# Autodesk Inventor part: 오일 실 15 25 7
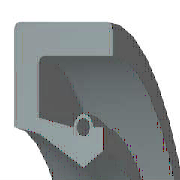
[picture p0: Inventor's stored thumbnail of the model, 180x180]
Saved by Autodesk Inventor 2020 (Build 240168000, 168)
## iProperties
Created: 2012-02
Part Number: 오일 실 15 25 7
Material: 고무
Description: 오일-실
Document SubType Name: Modeling
Standard: KS B 2804
Designer: mduedu
Standards Organization: KS
Language: ko-KR
Size Designation: S - 15 25 7
Categories: <MemberInstance><Categories><Category DisplayName="샤프트 부품" InternalName="7f7aeb1f-a693-4053-b835-cee3144e0d98" Mnemonic="SHFT"><Category DisplayName="실링" Intern
Density: 0.93 g/cm^3
Appearance: 고무 - 검은색 - 버전 1.1
IsCustomPart: 1
Author: mduedu
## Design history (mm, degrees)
revolve "본체" stored, may be unused: angle "d17" = 90 deg
revolve "스프링1" stored, may be unused: angle "d18" = 90 deg
body "Solid1"
sketch "스케치1"
  geometry: L1 (0, 12.5)-(7, 12.5); L2 (7, 12.5)-(7, 11.25); L3 (7, 11.25)-(1.75, 11.25); L4 (0, 12.5)-(0, 9.6); L5 (0, 9.6)-(1.75, 9.25); L6 (1.75, 9.25)-(4.9, 7.5); L7 (4.9, 7.5)-(0, 7.5); L8 (6.3, 8.375)-(6.3, 9.6); L9 (0, 0)-(9.586, 0) reference; L10 (4.9, 7.5)-(6.3, 8.375); L11 (0, 18)-(0, -3) reference; L12 (-1.917, 0)-(11.503, 0) reference; L13 (4.2, 9.6)-(1.75, 10.09); L14 (1.75, 10.09)-(1.75, 11.25); L15 (6.3, 9.6)-(5.6, 9.6); C1 r 0.455 at (4.9, 9.6); A1 r 0.7 centre (4.9, 9.6) between (5.6, 9.6) and (4.2, 9.6)
  constraints: 26 end point, 5 horizontal alignment, 4 perpendicular, 2 centre point, 2 collinear, 2 horizontal, 2 parallel, 2 point on circle, 2 point on line, 2 vertical alignment, 1 coincident
  dimensions: "d0" = 25 diameter of L1 L9 (= SD2); "d1" = 16.75 diameter of L8.start L9 (= ABDM); "d2" = 1.25 distance of L1.end L2.end (computed from SD); "d3" = 0.91 diameter of C1 (= SPDI); "d4" = 1.4 diameter of A1 (= SPDA); "d5" = 15 diameter of L6.end L9 (= NND); "d6" = 18.5 diameter of L5.end L9 (= TKDM); "d7" = 19.2 diameter of L4.end L9 (= HLDM); "d8" = 4.9 distance from line of C1.centre L4 (= SPDST); "d9" = 6.3 distance between parallel lines of L8 L4 (= SDI); "d10" = 7 distance between parallel lines of L2 L4 (= SWDT); "d12" = 1.75 distance between parallel lines of L14 L4 (= SD)
fillet "모깎기1" dims "d11" = 0.3 (= RR)
other parameters: "SD2" = 25 [user parameter; used in 1 equation term], "SWDT" = 7 [user parameter; used in 1 equation term], "RR" = 0.3 [user parameter; used in 1 equation term], "SD" = 1.75 [user parameter; used in 2 equation terms], "NND" = 15 [user parameter; used in 1 equation term], "SPDA" = 1.4 [user parameter; used in 1 equation term], "SPDI" = 0.91 [user parameter; used in 1 equation term], "TKDM" = 18.5 [user parameter; used in 1 equation term], "HLDM" = 19.2 [user parameter; used in 1 equation term], "ABDM" = 16.75 [user parameter; used in 1 equation term], "SDI" = 6.3 [user parameter; used in 1 equation term], "SPDST" = 4.9 [user parameter; used in 1 equation term], "d13" = 0, "d14" = 0, "d15" = 0, "LAB" = 0.35 [user parameter]
